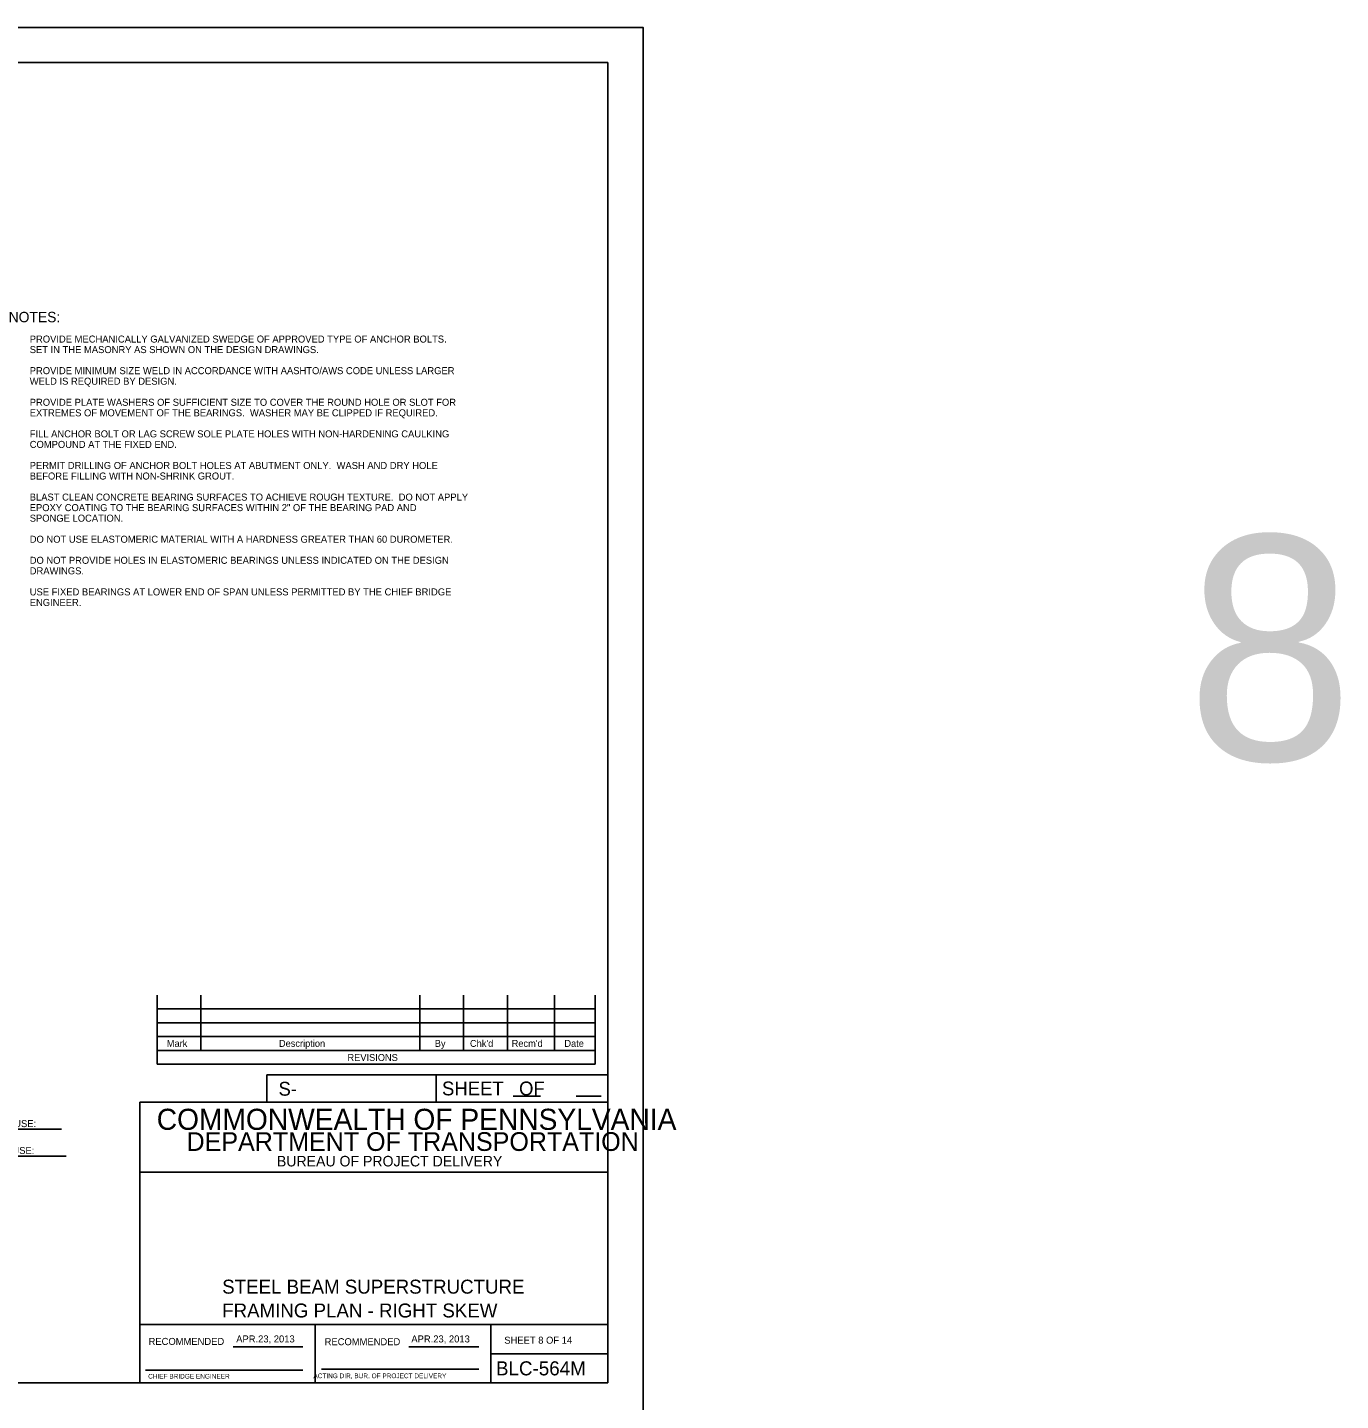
# Model space of a CAD drawing. Extents: x 638175 to 640495, y 294277 to 298435.
# Drawn here: x 639854 to 640415, y 297849 to 298435 of the extents above; entities that cross this region are included whole.
import ezdxf

# ---------------------------------------------------------------- set-up
doc = ezdxf.new("R2010")
doc.units = 0
for name, color, linetype in [('1', 7, 'Continuous'), ('2', 7, 'Continuous'), ('4', 7, 'Continuous'), ('53', 7, 'Continuous'), ('PLT-BNDY', 7, 'Continuous')]:
    doc.layers.add(name, color=color, linetype=linetype)

msp = doc.modelspace()

# ---------------------------------------------------------------- linework, layer by layer
at = {"layer": '2'}
for p, q in [((639316.46, 298420.46), (640102.46, 298420.46)), ((640102.46, 298420.46), (640102.46, 297856.46)), ((639909.92, 298022.15), (639909.92, 297992.62)), ((639928.62, 298022.15), (639928.62, 297998.53)), ((640022.13, 298022.15), (640022.13, 297998.53)), ((640040.83, 298022.15), (640040.83, 297998.53)), ((640059.53, 298022.15), (640059.53, 297998.53)), ((640079.59, 298022.15), (640079.59, 297998.53)), ((640096.94, 298022.15), (640096.94, 297992.62)), ((640096.94, 298016.24), (639909.92, 298016.24)), ((640096.94, 298010.34), (639909.92, 298010.34)), ((640096.94, 298004.43), (639909.92, 298004.43)), ((640096.94, 297998.53), (639909.92, 297998.53)), ((640096.94, 297992.62), (639909.92, 297992.62)), ((640102.46, 297988.11), (639956.78, 297988.11)), ((639956.78, 297988.11), (639956.78, 297976.46)), ((640029.09, 297988.11), (640029.09, 297976.46)), ((640061.95, 297979), (640073.6, 297979)), ((640088.83, 297979), (640099.56, 297979)), ((640102.46, 297976.46), (639902.46, 297976.46)), ((639902.46, 297976.46), (639902.46, 297856.46)), ((640102.46, 297946.46), (639902.46, 297946.46)), ((640102.46, 297881.46), (639902.46, 297881.46)), ((639977.46, 297856.46), (639977.46, 297881.46)), ((640052.46, 297881.46), (640052.46, 297856.46)), ((639942.42, 297871.96), (639972.19, 297871.96)), ((640017.42, 297871.96), (640047.33, 297871.96)), ((640052.46, 297868.96), (640102.46, 297868.96)), ((639904.96, 297861.96), (639972.19, 297861.96)), ((639980.08, 297862.33), (640047.33, 297862.33)), ((640102.46, 297856.46), (639316.46, 297856.46))]:
    msp.add_line(p, q, dxfattribs=at)
at = {"layer": '4'}
for p, q in [((639810.84, 297964.94), (639869, 297964.94)), ((639812.05, 297953.35), (639871.08, 297953.35))]:
    msp.add_line(p, q, dxfattribs=at)
at = {"layer": 'PLT-BNDY'}
msp.add_lwpolyline([(639276.46, 298435.46), (640117.46, 298435.46), (640117.46, 297841.46), (639276.46, 297841.46)], close=True, dxfattribs=at)

# ---------------------------------------------------------------- texts
at = {"layer": '1'}
msp.add_text('SHEET 8 OF 14', height=3, dxfattribs=at).set_placement((640058.19, 297873.22))
at = {"layer": '2'}
for s, height, p in [('Mark', 2.952, (639914.02, 298000.03)), ('Description', 2.9523, (639961.92, 298000.03)), ('By', 2.952, (640028.49, 298000.03)), ("Chk'd", 2.952, (640043.52, 298000.03)), ("Recm'd", 2.953, (640061.33, 298000.03)), ('Date', 2.952, (640083.86, 298000.03)), ('REVISIONS', 2.952, (639991.2, 297994.01)), ('S-', 5.905, (639961.73, 297979.17)), ('COMMONWEALTH OF PENNSYLVANIA', 9, (639909.71, 297964.58)), ('DEPARTMENT OF TRANSPORTATION', 8.0002, (639922.46, 297955.58)), ('BUREAU OF PROJECT DELIVERY', 4.5, (639961.05, 297948.96)), ('APR.23, 2013', 3, (639943.67, 297873.77)), ('APR.23, 2013', 3, (640018.48, 297873.77)), ('BLC-564M', 6, (640054.64, 297859.71)), ('CHIEF BRIDGE ENGINEER', 2.0002, (639906.05, 297858.33)), ('  ACTING DIR, BUR. OF PROJECT DELIVERY', 2.0002, (639975.11, 297858.51))]:
    msp.add_text(s, height=height, dxfattribs=at).set_placement(p)
for s, height, p in [('SHEET   OF', 5.907, (640031.58, 297979.31)), ('RECOMMENDED', 3, (639906.23, 297872.71)), ('RECOMMENDED', 3, (639981.44, 297872.58))]:
    msp.add_text(s, height=height, rotation=360, dxfattribs=at).set_placement(p)
at = {"layer": '4'}
for s, height, p in [('NOTES:', 4.429, (639846.47, 298309.55)), ('PROVIDE MECHANICALLY GALVANIZED SWEDGE OF APPROVED TYPE OF ANCHOR BOLTS.', 3, (639855.47, 298300.86)), ('SET IN THE MASONRY AS SHOWN ON THE DESIGN DRAWINGS.', 3, (639855.47, 298296.36)), ('PROVIDE MINIMUM SIZE WELD IN ACCORDANCE WITH AASHTO/AWS CODE UNLESS LARGER', 3, (639855.47, 298287.36)), ('WELD IS REQUIRED BY DESIGN.', 3, (639855.47, 298282.86)), ('PROVIDE PLATE WASHERS OF SUFFICIENT SIZE TO COVER THE ROUND HOLE OR SLOT FOR', 3, (639855.47, 298273.86)), ('EXTREMES OF MOVEMENT OF THE BEARINGS.  WASHER MAY BE CLIPPED IF REQUIRED.', 3, (639855.47, 298269.36)), ('COMPOUND AT THE FIXED END.', 3, (639855.47, 298255.86)), ('FILL ANCHOR BOLT OR LAG SCREW SOLE PLATE HOLES WITH NON-HARDENING CAULKING ', 3, (639855.47, 298260.36)), ('PERMIT DRILLING OF ANCHOR BOLT HOLES AT ABUTMENT ONLY.  WASH AND DRY HOLE', 3, (639855.47, 298246.86)), ('BEFORE FILLING WITH NON-SHRINK GROUT.', 3, (639855.47, 298242.36)), ('BLAST CLEAN CONCRETE BEARING SURFACES TO ACHIEVE ROUGH TEXTURE.  DO NOT APPLY', 3, (639855.47, 298233.36)), ('EPOXY COATING TO THE BEARING SURFACES WITHIN 2" OF THE BEARING PAD AND', 3, (639855.47, 298228.86)), ('SPONGE LOCATION.', 3, (639855.47, 298224.36)), ('DO NOT USE ELASTOMERIC MATERIAL WITH A HARDNESS GREATER THAN 60 DUROMETER.', 3, (639855.47, 298215.36)), ('DO NOT PROVIDE HOLES IN ELASTOMERIC BEARINGS UNLESS INDICATED ON THE DESIGN', 3, (639855.47, 298206.36)), ('DRAWINGS.', 3, (639855.47, 298201.86)), ('USE FIXED BEARINGS AT LOWER END OF SPAN UNLESS PERMITTED BY THE CHIEF BRIDGE ', 3, (639855.47, 298192.86)), ('ENGINEER.', 3, (639855.47, 298188.36)), ('FOR CONC. ABUT. USE:', 3, (639812.3, 297965.74)), ('FOR TIMBER SILL USE:', 3, (639812.86, 297954.27)), ('STEEL BEAM SUPERSTRUCTURE', 5.9714, (639937.69, 297894.61)), ('FRAMING PLAN - RIGHT SKEW', 5.9714, (639937.68, 297884.43))]:
    msp.add_text(s, height=height, dxfattribs=at).set_placement(p)
at = {"layer": '53'}
msp.add_text('8', height=96, dxfattribs=at).set_placement((640349.58, 298122.42))

doc.saveas('drawing.dxf')
